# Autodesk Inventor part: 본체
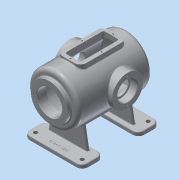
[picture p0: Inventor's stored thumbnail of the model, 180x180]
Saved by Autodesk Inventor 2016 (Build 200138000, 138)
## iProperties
Created: 2016-02
Part Number: 본체
Material: 알루미늄 6061
Document SubType Name: Modeling
Designer: mduedu
Density: 2.71 g/cm^3
Appearance: 알루미늄 - 평지
Mass: 3305.63 g
Surface Area: 2487.05 cm^2
Volume: 1219.79 cm^3
Author: mduedu
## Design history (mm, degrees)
sketch "스케치2"
  geometry: L1 (0, 100)-(0, -100); L2 (65, -87.083)-(65, 100); L3 (65, 100)-(0, 100); A1 r 170 centre (0, 70) between (0, -100) and (65, -87.083); 2 further points
  constraints: 6 end point, 2 point on circle, 1 centre point, 1 coincident, 1 horizontal, 1 midpoint, 1 parallel, 1 point on line, 1 vertical
  dimensions: "d3" = 200 distance of L1.start L1.end; "d5" = 130 diameter of L2 L1; "d6" = 170 radius of A1
revolve "회전1" sketch "스케치2" stored, may be unused: angle "d7" = 90 deg
sketch "스케치3"
  geometry: C1 r 47.5 at (0, 0); 1 further point
  constraints: 1 centre point, 1 coincident
  dimensions: "d8" = 95 diameter of C1
extrude "돌출2" join sketch "스케치3" distance "d10" = 10; taper "d11" = 0 deg
sketch "스케치5"
  geometry: L1 (47.5, 110)-(47.5, 100) reference; L2 (47.5, 100)-(65, 100) reference; L3 (65, 100)-(65, -87.083) reference; L4 (-65, -87.083)-(-65, 100) reference; L5 (-65, 100)-(-47.5, 100) reference; L6 (-47.5, 100)-(-47.5, 110) reference; L7 (-47.5, 110)-(47.5, 110) reference; L8 (55, 85)-(55, -80.25); L9 (0, 85)-(55, 85); L10 (0, 85)-(0, -90); A1 r 170 centre (0, 70) between (-65, -87.083) and (0, -100) reference; A2 r 170 centre (0, 70) between (0, -100) and (65, -87.083) reference; A3 r 160 centre (0, 70) between (0, -90) and (55, -80.25); 1 further point
  constraints: 6 end point, 2 point on circle, 1 centre point, 1 parallel, 1 perpendicular, 1 point on line, 1 vertical
  dimensions: "d13" = 10 distance between parallel lines of L3 L8; "d14" = 10 radial gap between concentric circles of A3 A1; "d15" = 15 distance between parallel lines of L9 L2
revolve "회전2" sketch "스케치5" stored, may be unused: angle "d16" = 90 deg
hole "구멍1" diameter "d19" = 65; stored, may be unused: countersink angle "d23" = 90 deg, drill point angle "d25" = 118 deg; dims "d17" = 10, "d18" = 10, "d20" = 6, "d21" = 4, "d22" = 2, "d24" = 8
node "작업 평면1"
sketch "스케치6"
  geometry: L1 (47.5, 110)-(-47.5, 110) reference; C1 r 40 at (0, -17); 1 further point
  constraints: 1 centre point, 1 vertical alignment
  dimensions: "d27" = 80 diameter of C1; "d29" = 127 distance from line of C1.centre L1
extrude "돌출3" join sketch "스케치6" stored distance "d30" = 10; taper "d31" = 0 deg
hole "구멍2" diameter "d34" = 42; stored, may be unused: countersink angle "d38" = 90 deg, drill point angle "d40" = 118 deg; dims "d32" = 10, "d33" = 10, "d35" = 6, "d36" = 52, "d37" = 18, "d39" = 8
sketch "스케치7" dims "d41" = 65
  geometry: C1 r 40 at (0, 0) reference; 3 further points
  constraints: 2 vertical alignment, 1 coincident, 2 other
hole "구멍3" sketch "스케치7" at (0, 32.5) diameter "d43" = 3.242; stored, may be unused: countersink angle "d47" = 90 deg, drill point angle "d49" = 118 deg; dims "d44" = 11, "d45" = 13, "d46" = 18, "d48" = 13
sketch "스케치8" dims "d53" = 80
  geometry: 3 further points
  constraints: 2 vertical alignment, 1 coincident, 2 other
hole "구멍4" sketch "스케치8" at (0, 40) diameter "d56" = 3.242; stored, may be unused: countersink angle "d60" = 90 deg, drill point angle "d62" = 118 deg; dims "d57" = 11, "d58" = 13, "d59" = 18, "d61" = 13
fillet "모깎기1" dims "d66" = 10
fillet "모깎기2" dims "d67" = 3
fillet "모깎기3" dims "d68" = 0.3
chamfer "모따기1" distance "d69" = 1; stored, may be unused: second distance "d70" = 2, angle "d71" = 45 deg
node "작업 평면2"
sketch "스케치9"
  geometry: L1 (75, 100)-(-75, 100); L2 (-75, 100)-(-75, -100); L3 (-75, -100)-(75, -100); L4 (75, -100)-(75, 100); 1 further point
  constraints: 8 end point, 2 parallel, 1 horizontal, 1 perpendicular
  dimensions: "d73" = 200 distance of L3.end L1.start; "d75" = 150 distance of L2.end L3.end; "d76" = 100 distance from line of L1 point (0, 0); "d77" = 75 distance from line of L4 point (0, 0)
extrude "돌출4" join sketch "스케치9" distance "d78" = 10; taper "d79" = 0 deg
sketch "스케치10"
  geometry: L1 (-75, -100)-(75, -100) reference; L2 (75, 100)-(-75, 100) reference; L3 (0, -100)-(0, 100); L4 (-75, 100)-(-75, -100) reference; L5 (75, -100)-(75, 100) reference; L6 (-75, 0)-(75, 0); L7 (-50, -63)-(50, -63); L8 (50, -63)-(50, -55); L9 (50, -55)-(-50, -55); L10 (-50, -55)-(-50, -63); L11 (-50, 63)-(50, 63); L12 (50, 63)-(50, 55); L13 (50, 55)-(-50, 55); L14 (-50, 55)-(-50, 63); 1 further point
  constraints: 20 end point, 4 midpoint, 4 symmetric about line, 2 parallel, 1 horizontal, 1 perpendicular, 1 other
  dimensions: "d80" = 8 distance of L9.end L7.start; "d82" = 100 distance of L7.start L7.end; "d83" = 55 distance between parallel lines of L9 L6
extrude "돌출5" join sketch "스케치10" stored distance "d84" = 10; taper "d85" = 0 deg
feature "면 기울기1" dims angle "d86" = 10 deg
sketch "스케치11"
  geometry: L1 (-110, 55)-(-51.482, 55) reference; L2 (-110, -55)-(-51.482, -55) reference; L3 (-95, 55)-(-95, -55); L4 (-65, 90)-(-65, -80.25) reference; 1 further point
  constraints: 2 end point, 2 point on line, 1 perpendicular
  dimensions: "d87" = 30 distance between parallel lines of L3 L4
feature "리브1" sketch "스케치11" dims "d88" = 1, "d89" = 8, "d90" = 0, "d91" = 0, "d92" = 1, "d93" = 1
sketch "스케치12"
  geometry: L1 (-110, 55)-(-51.482, 55) reference; L2 (-110, -55)-(-51.482, -55) reference; L3 (-110, 100)-(-110, -100) reference; L4 (-120, 152)-(-120, -142) reference; L5 (-110, 45)-(-120, 45); L6 (-120, 45)-(-120, -45); L7 (-120, -45)-(-110, -45); L8 (-110, -45)-(-110, 45); 1 further point
  constraints: 8 end point, 2 parallel, 2 point on line, 1 horizontal, 1 perpendicular
  dimensions: "d94" = 10 distance between parallel lines of L7 L2; "d95" = 10 distance between parallel lines of L1 L5
extrude "돌출6" cut sketch "스케치12" stored distance "d96" = 10; taper "d97" = 0 deg
fillet "모깎기4" dims "d98" = 15
sketch "스케치13"
  geometry: C1 r 5 at (-60, -85); C2 r 5 at (60, -85); C3 r 5 at (60, 85); C4 r 5 at (-60, 85); A1 r 15 centre (-60, -85) between (-75, -85) and (-60, -100) reference; A2 r 15 centre (60, -85) between (60, -100) and (75, -85) reference; A3 r 15 centre (60, 85) between (75, 85) and (60, 100) reference; A4 r 15 centre (-60, 85) between (-60, 100) and (-75, 85) reference; 1 further point
  constraints: 4 centre point, 4 coincident, 3 equal radius
  dimensions: "d99" = 10 diameter of C1
extrude "돌출7" cut sketch "스케치13" stored distance "d101" = 10; taper "d102" = 0 deg
fillet "모깎기5" dims "d103" = 3, "d104" = 3
fillet "모깎기6" dims "d105" = 3
sketch "스케치14"
  geometry: L1 (-60, -100)-(60, -100) reference; 2 further points
  constraints: 1 vertical alignment, 1 other
  dimensions: "d106" = 15 distance from line of point (0, -85) L1
feature "엠보싱1" sketch "스케치14" dims "d3" = 200, "d5" = 130, "d6" = 170, "d14" = 10, "d107" = 0.5, "d108" = 0
node "작업 평면3"
sketch "스케치15"
  geometry: L1 (-30, 60)-(30, 60); L2 (30, 60)-(30, -60); L3 (30, -60)-(-30, -60); L4 (-30, -60)-(-30, 60); 2 further points
  constraints: 8 end point, 2 parallel, 1 horizontal, 1 midpoint, 1 perpendicular, 1 vertical alignment
  dimensions: "d110" = 60 distance of L2.end L3.end; "d112" = 60 distance from line of L3 point (0, 0); "d113" = 120 distance of L1.end L2.end
extrude "돌출8" join sketch "스케치15" stored distance "d114" = 10; taper "d115" = 0 deg
fillet "모깎기7" dims "d116" = 15
sketch "스케치16"
  geometry: L1 (-30, -45)-(-30, 45) reference; L2 (-15, 60)-(15, 60) reference; L3 (30, 45)-(30, -45) reference; L4 (15, -60)-(-15, -60) reference; L5 (15, 50)-(-15, 50); L6 (-20, 45)-(-20, -45); L7 (-15, -50)-(15, -50); L8 (20, -45)-(20, 45); A1 r 15 centre (-15, -45) between (-30, -45) and (-15, -60) reference; A2 r 15 centre (-15, 45) between (-15, 60) and (-30, 45) reference; A3 r 15 centre (15, 45) between (30, 45) and (15, 60) reference; A4 r 15 centre (15, -45) between (15, -60) and (30, -45) reference; A5 r 5 centre (-15, 45) between (-15, 50) and (-20, 45); A6 r 5 centre (-15, -45) between (-20, -45) and (-15, -50); A7 r 5 centre (15, -45) between (15, -50) and (20, -45); A8 r 5 centre (15, 45) between (20, 45) and (15, 50); 1 further point
  constraints: 8 end point, 8 point on circle, 4 centre point, 7 other
  dimensions: "d117" = 10 distance between parallel lines of L6 L1
extrude "돌출9" cut sketch "스케치16" stored distance "d118" = 10; taper "d119" = 0 deg
fillet "모깎기8" dims "d120" = 3
sketch "스케치17"
  geometry: L1 (-30, -45)-(-30, 45) reference; L2 (-15, 60)-(15, 60) reference; L3 (30, 45)-(30, -45) reference; L4 (15, -60)-(-15, -60) reference; L5 (20, -45)-(20, 45) reference; L6 (15, 50)-(-15, 50) reference; L7 (-20, 45)-(-20, -45) reference; L8 (-15, -50)-(15, -50) reference; L9 (15, 55)-(-15, 55); L10 (-25, 45)-(-25, -45); L11 (-15, -55)-(15, -55); L12 (25, -45)-(25, 45); A1 r 15 centre (-15, 45) between (-15, 60) and (-30, 45) reference; A2 r 15 centre (15, 45) between (30, 45) and (15, 60) reference; A3 r 15 centre (15, -45) between (15, -60) and (30, -45) reference; A4 r 15 centre (-15, -45) between (-30, -45) and (-15, -60) reference; A5 r 5 centre (15, -45) between (15, -50) and (20, -45) reference; A6 r 5 centre (15, 45) between (20, 45) and (15, 50) reference; A7 r 5 centre (-15, 45) between (-15, 50) and (-20, 45) reference; A8 r 5 centre (-15, -45) between (-20, -45) and (-15, -50) reference; A9 r 10 centre (-15, 45) between (-15, 55) and (-25, 45); A10 r 10 centre (-15, -45) between (-25, -45) and (-15, -55); A11 r 10 centre (15, -45) between (15, -55) and (25, -45); A12 r 10 centre (15, 45) between (25, 45) and (15, 55); 5 further points
  constraints: 8 end point, 8 point on circle, 4 centre point, 4 midpoint, 7 other
  dimensions: "d121" = 5 distance between parallel lines of L10 L1
hole "구멍5" sketch "스케치17" at (0, 55), (25, 0), (0, -55), (-25, 0) diameter "d122" = 3.242; stored, may be unused: countersink angle "d126" = 90 deg, drill point angle "d128" = 118 deg; dims "d123" = 9, "d124" = 13, "d125" = 18, "d127" = 11
fillet "모깎기9" dims "d129" = 3
node "솔리드2"
pattern_circular "원형 패턴1" dims angle "d51" = 360 deg
mirror "대칭1"
pattern_circular "원형 패턴2" dims angle "d64" = 360 deg
node "절단 모서리 투영1"
node "절단 모서리 투영2"
node "절단 모서리 투영3"
other parameters: "d26" = 75
